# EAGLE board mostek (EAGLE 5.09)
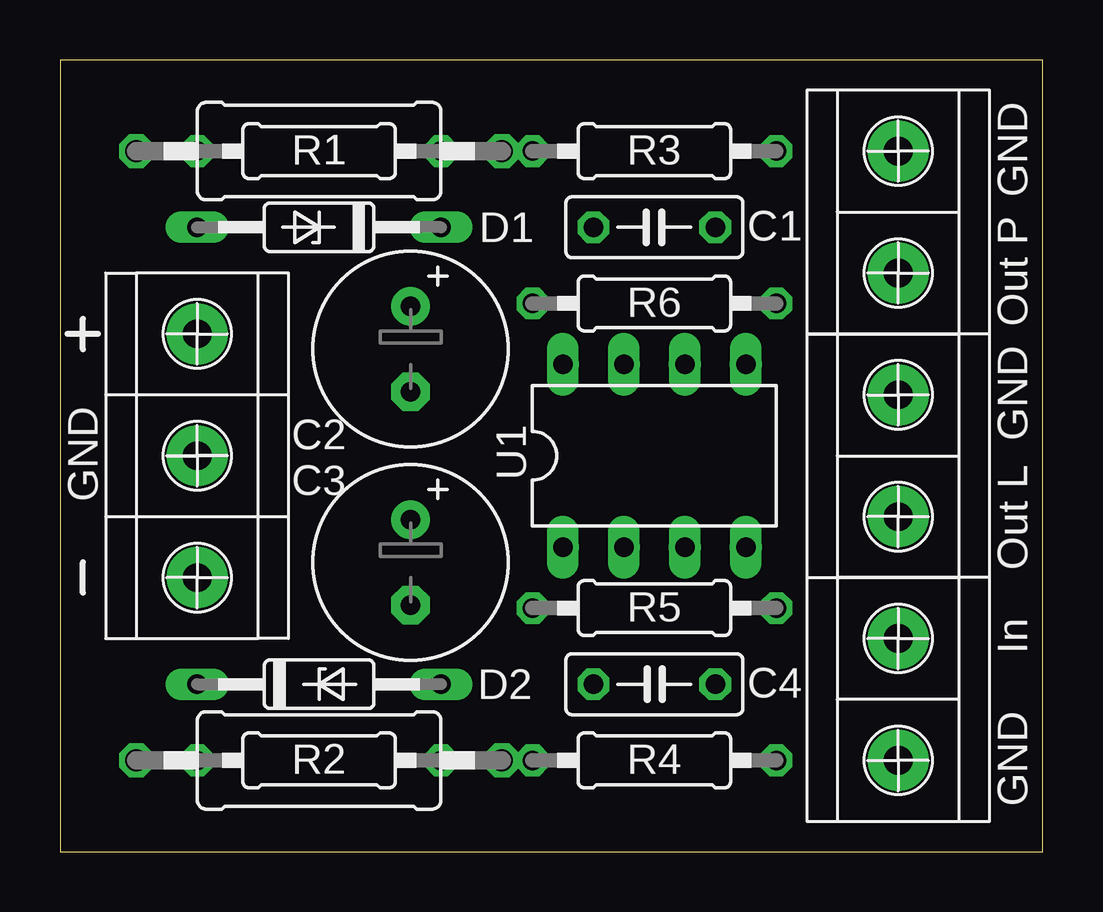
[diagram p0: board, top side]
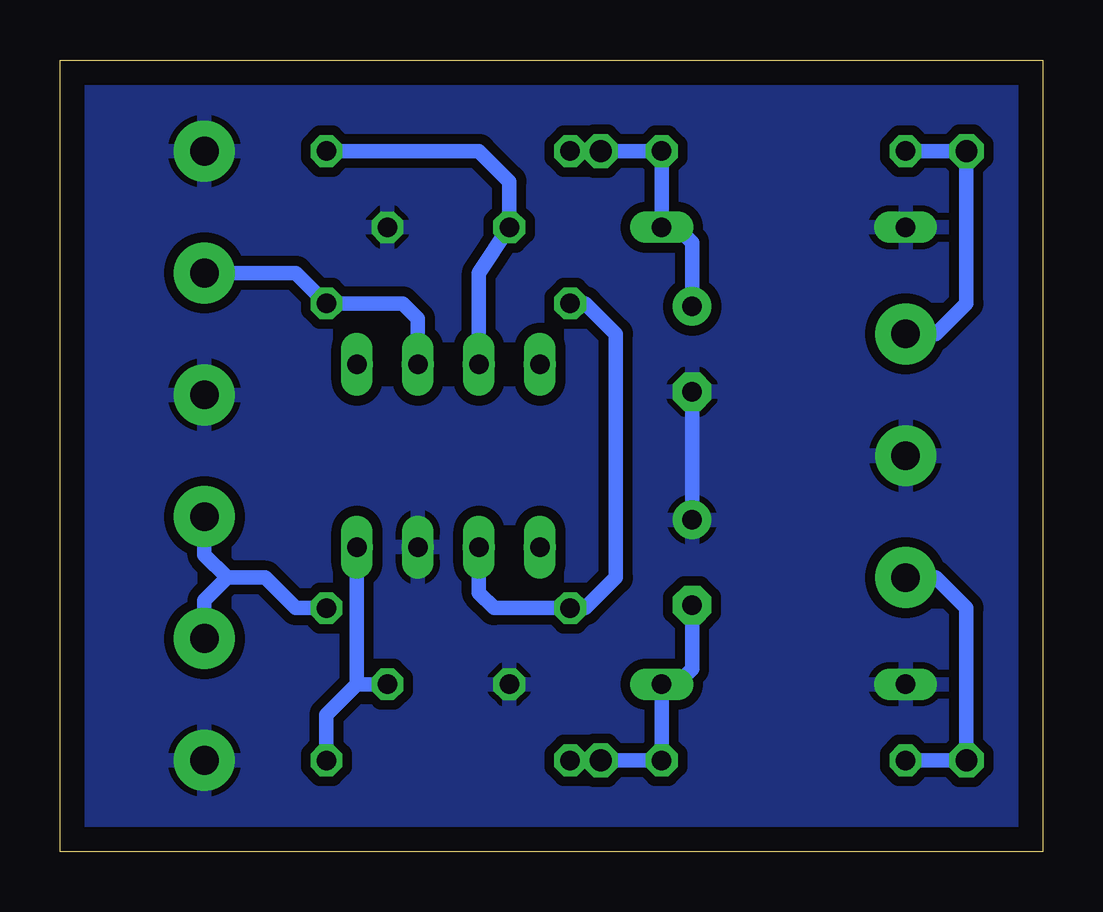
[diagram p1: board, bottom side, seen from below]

Size 40.94 x 33.01 mm. Coordinates in mm from the lower left corner, seen from the top.
Outline: 0,0 40.94,0 40.94,33.01 0,33.01 0,0
Copper layers (1*16): Top 0.035mm / dielectric 1.5mm / Bottom 0.035mm
Design rules "default": minimum track width 10mil, minimum drill 24mil, track to track 8mil, track to pad 8mil, pad to pad 8mil, via to via 8mil, smd to smd 8mil, copper to edge 40mil, drill to drill 8mil, minimum pad ring 10mil, minimum via ring 8mil, stop-mask expansion 4mil, vias tented up to drill 0mil, thermal gap 10mil

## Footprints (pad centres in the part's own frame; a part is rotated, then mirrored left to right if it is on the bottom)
C050-025X075 = drill 0.813 octagon: 1 -2.54,0; 2 2.54,0
E3,5-8 = drill 0.813 pad 1.6 round: + -1.778,0 | drill 0.813 pad 1.6 octagon: - 1.778,0
DO35Z10 = drill 0.813 long: A 5.08,0; C -5.08,0
DIL08 = drill 0.813 long: 1 -3.81,-3.81; 2 -1.27,-3.81; 3 1.27,-3.81; 4 3.81,-3.81; 5 3.81,3.81; 6 1.27,3.81; 7 -1.27,3.81; 8 -3.81,3.81
0207/10 = drill 0.813 octagon: 1 -5.08,0; 2 5.08,0
0411/15 = drill 0.914 octagon: 1 -7.62,0; 2 7.62,0
DIL08' = drill 0.813 pad 1.27 round: 1 -3.81,-3.81; 2 -1.27,-3.81; 3 1.27,-3.81; 4 3.81,-3.81; 5 3.81,3.81; 6 1.27,3.81; 7 -1.27,3.81; 8 -3.81,3.81
ARK2 = drill 1.2 pad 2.54 round: 1 -2.54,0; 3 2.54,0 | drill 0.8 pad 2.54 round: 2 2.54,0

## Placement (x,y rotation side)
C1  [C050-025X075]  24.77,26.04 180 top
C2  [E3,5-8]  14.61,20.95 270 top
C3  [E3,5-8]  14.61,12.06 270 top
C4  [C050-025X075]  24.77,6.98 0 top
D1  ZPD  [DO35Z10]  10.79,26.04 180 top
D2  ZPD  [DO35Z10]  10.79,6.98 0 top
IC2  [DIL08]  24.77,16.51 0 top
R1  [0207/10]  10.79,29.21 180 top
R2  [0207/10]  10.79,3.81 180 top
R3  [0207/10]  24.77,29.21 180 top
R4  [0207/10]  24.77,3.81 180 top
R5  [0207/10]  24.77,10.16 0 top
R6  [0207/10]  24.77,22.86 0 top
R7  [0411/15]  10.79,29.21 0 top
R8  [0411/15]  10.79,3.81 0 top
U1  TL071P  [DIL08']  24.77,16.51 0 top
U$1  ARK2  [ARK2]  34.92,6.35 90 top
U$2  ARK2  [ARK2]  5.71,13.97 270 top
U$3  ARK2  [ARK2]  5.71,19.05 90 top
U$4  ARK2  [ARK2]  34.92,26.67 270 top
U$5  ARK2  [ARK2]  34.92,16.51 270 top

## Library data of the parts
C1-C4 R1-R8 = rcl
D1 D2 = diode
IC2 = ic-package
U1 = linear
U$1-U$5 = ark2

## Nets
GND: C1.1 C2.- C3.+ C4.1 D1.A D2.C IC2.3 U1.3 U$1.1 U$2.1 U$3.1 U$4.1 U$5.1
N$4: R1.2 R7.1 U$3.2
N$5: R2.2 R8.1 U$2.2
N$6: C2.+ D1.C R1.1 R3.2 R7.2
N$7: C3.- D2.A R2.1 R4.2 R8.2
N$8: C4.2 R4.1 U1.4
N$9: C1.2 R3.1 U1.7
N$10: R5.1 R6.1 U1.2
N$11: R6.2 U1.6 U$4.2
N$12: R5.2 U$1.2 U$5.2

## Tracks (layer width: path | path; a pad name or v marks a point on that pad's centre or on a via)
GND
  Bottom 0.61: C3.+ C2.-
  pour Bottom (isolate 0.406): -0.63,33.65 41.27,33.65 41.27,-0.63 -0.63,-0.63
N$4
  Bottom 0.61: U$3.2 4.45,21.59 3.18,22.86 R7.1 R1.2
N$5
  Bottom 0.61: R2.2 R8.1 3.18,10.16 4.45,11.43 U$2.2
N$6
  Bottom 0.61: C2.+ 14.61,25.4 15.24,26.04 D1.C R1.1 R7.2 R3.2
N$7
  Bottom 0.61: C3.- 14.61,7.62 15.24,6.98 D2.A R2.1 R8.2 R4.2
N$8
  Bottom 0.61: 28.57,6.98 U1.4 | 28.57,6.98 29.85,5.72 R4.1 | C4.2 28.57,6.98
N$9
  Bottom 0.61: U1.7 23.5,24.13 C1.2 22.22,27.94 23.5,29.21 R3.1
N$10
  Bottom 0.61: U1.2 23.5,10.8 22.86,10.16 R5.1 19.05,10.16 17.78,11.43 17.78,21.59 19.05,22.86 R6.1
N$11
  Bottom 0.61: U1.6 26.04,22.23 26.67,22.86 R6.2 31.11,24.13 U$4.2
N$12
  Bottom 0.61: R5.2 31.11,10.16 32.39,11.43 33.97,11.43 | U$5.2 34.92,12.38 33.97,11.43 | 33.97,11.43 34.92,10.48 U$1.2

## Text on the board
tPlace: GND | Out P | GND | GND | Out L | In | GND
